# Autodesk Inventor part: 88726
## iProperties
Created: 2005-11
Part Number: 88726
Material: 1.4301 X5CrNi10-10 A2
Description: Rohrbogen (A2- 90grd.) DN 100 ISO-K
Document SubType Name: Modellieren
Designer: Mittelmeyer
Manufacturer: Standard
Standards Organization: Custom
Vendor: LEYBOLD
Author: Mittelmeyer
Comments: LEYBOLD
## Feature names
1. Extrusion2
2. Extrusion3
3. Extrusion4
4. Drehung1 [Revolution]
5. Bohrung1 [Hole]
6. Extrusion5
7. Runde Anordnung1 [Circular Pattern]
8. Sweeping2
